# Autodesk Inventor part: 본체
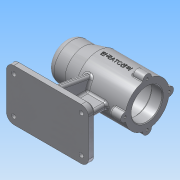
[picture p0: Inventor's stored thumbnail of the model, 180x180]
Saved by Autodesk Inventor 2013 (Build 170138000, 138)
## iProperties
Created: 2019-07
Part Number: 본체
Material: 알루미늄 6061
Document SubType Name: Modeling
Designer: Administrator
Density: 2.71 g/cm^3
Mass: 658.039 g
Surface Area: 650.148 cm^2
Volume: 242.819 cm^3
Author: Administrator
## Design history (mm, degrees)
sketch "스케치1"
  geometry: L1 (56, 0)-(-56, 0); L2 (56, 0)-(56, 30); L3 (56, 30)-(-11, 30); L4 (-11, 30)-(-31, 25); L5 (-31, 25)-(-56, 25); L6 (-56, 25)-(-56, 0); 2 further points
  constraints: 12 end point, 2 parallel, 2 perpendicular, 1 coincident, 1 horizontal, 1 midpoint
  dimensions: "d1" = 60 diameter of L3 L1; "d3" = 50 diameter of L5 L1; "d4" = 25 distance of L4.end L5.end; "d5" = 45 distance from line of L6 L3.end; "d7" = 112 distance between parallel lines of L6 L2
revolve "회전1" sketch "스케치1" stored, may be unused: angle "d8" = 90 deg
node "작업 평면1"
sketch "스케치2"
  geometry: L1 (-56, 35)-(56, 35); L2 (56, 35)-(56, -35); L3 (56, -35)-(-56, -35); L4 (-56, -35)-(-56, 35); 3 further points
  constraints: 8 end point, 2 midpoint, 2 parallel, 1 horizontal, 1 horizontal alignment, 1 perpendicular, 1 vertical alignment
  dimensions: "d10" = 112 distance of L1.start L1.end; "d12" = 70 distance of L3.end L1.start
extrude "돌출1" join sketch "스케치2" distance "d13" = 10; taper "d14" = 0 deg
sketch "스케치3"
  geometry: L1 (31, 0)-(31, -70); L2 (31, -70)-(-36, -70); L3 (-36, -70)-(-10.522, 0); L4 (-10.522, 0)-(31, 0); L5 (56, -80)-(56, -70) reference; L6 (-56, -80)-(-56, -70) reference; L7 (56, -70)-(-56, -70) reference; 3 further points
  constraints: 8 end point, 2 horizontal alignment, 2 midpoint, 1 parallel, 1 perpendicular, 1 vertical
  dimensions: "d15" = 25 distance between parallel lines of L5 L1; "d16" = 20 distance from line of L2.end L6; "d17" = 110 deg angle of L3 L7
extrude "돌출2" join sketch "스케치3" distance "d18" = 4; taper "d20" = 0 deg; dims "d19" = 4, "d21" = 0
sketch "스케치4"
  geometry: L1 (-22.666, 19.654)-(-70, 28); L2 (-70, -35)-(-70, 35) reference; L3 (-80, 35)-(-70, 35) reference; A1 r 30 centre (0, 0) between (-29.732, -4) and (-29.732, 4) reference; 1 further point
  constraints: 2 end point, 1 point on circle, 1 point on line
  dimensions: "d22" = 100 deg angle of L1 L2; "d23" = 7 distance from line of L1.end L3
feature "리브1" sketch "스케치4" dims "d24" = 1, "d25" = 8, "d26" = 0, "d27" = 0, "d28" = 1, "d29" = 1
sketch "스케치5"
  geometry: L1 (56, -30)-(56, 30) reference; L2 (-56, -25)-(-56, 25) reference; L3 (56, 0)-(-50, 0); L4 (56, 0)-(56, 21); L5 (56, 21)-(41, 21); L6 (41, 21)-(41, 24); L7 (41, 24)-(-13, 24); L8 (-13, 24)-(-13, 21); L9 (-13, 21)-(-25, 21); L10 (-25, 21)-(-25, 17.5); L11 (-25, 17.5)-(-43, 17.5); L12 (-43, 17.5)-(-43, 16); L13 (-43, 16)-(-47, 16); L14 (-47, 16)-(-47, 10.5); L15 (-47, 10.5)-(-50, 10.5); L16 (-50, 10.5)-(-50, 0); 1 further point
  constraints: 28 end point, 8 parallel, 4 perpendicular, 1 collinear, 1 midpoint, 1 point on line
  dimensions: "d30" = 42 diameter of L5 L3; "d32" = 48 diameter of L7 L3; "d33" = 42 diameter of L9 L3; "d34" = 21 diameter of L15 L3; "d35" = 32 diameter of L13 L3; "d36" = 35 diameter of L11 L3; "d37" = 3 distance of L14.end L15.end; "d38" = 4 distance of L12.end L13.end; "d39" = 18 distance of L10.end L11.end; "d40" = 12 distance of L8.end L9.end; "d41" = 54 distance of L6.end L7.end; "d42" = 15 distance of L4.end L5.end
revolve "회전2" sketch "스케치5" stored, may be unused: angle "d43" = 90 deg
sketch "스케치6"
  geometry: C1 r 21 at (0, 0) reference; C2 r 6 at (0, 30); 1 further point
  constraints: 2 vertical alignment, 1 centre point, 1 other
  dimensions: "d44" = 12 diameter of C2
extrude "돌출3" join sketch "스케치6" distance "d45" = 16; taper "d46" = 0 deg
fillet "모깎기1" dims "d50" = 10, "d51" = 3, "d56" = 0.3
fillet "모깎기2" dims "d52" = 1, "d57" = 3
chamfer "모따기1" distance "d53" = 3; stored, may be unused: second distance "d54" = 2, angle "d55" = 45 deg
sketch "스케치7"
  geometry: A1 r 7 centre (46, -25) between (46, -32) and (53, -25) reference; A2 r 7 centre (46, 25) between (53, 25) and (46, 32) reference; A3 r 7 centre (-46, 25) between (-46, 32) and (-53, 25) reference; A4 r 7 centre (-46, -25) between (-53, -25) and (-46, -32) reference; 1 further point
hole "구멍1" sketch "스케치7" at (-46, 25), (-46, -25), (46, -25), (46, 25) diameter "d58" = 6; stored, may be unused: countersink angle "d62" = 90 deg, drill point angle "d64" = 118 deg; dims "d59" = 6, "d60" = 4, "d61" = 2, "d63" = 8
sketch "스케치8"
  geometry: A1 r 6 centre (30, 30) between (35.998, 30.171) and (24.002, 30.171) reference; A2 r 6 centre (0, 0) between (-0.171, 5.998) and (-0.171, -5.998) reference; A3 r 6 centre (30, -30) between (24.002, -30.171) and (35.998, -30.171) reference; A4 r 6 centre (60, 0) between (60.171, -5.998) and (60.171, 5.998) reference
hole "구멍2" sketch "스케치8" at (30, 30), (0, 0), (30, -30), (60, 0) diameter "d65" = 3.242; stored, may be unused: countersink angle "d69" = 90 deg, drill point angle "d71" = 118 deg; dims "d66" = 8, "d67" = 4, "d68" = 2, "d70" = 11
node "작업 평면2"
sketch "스케치9"
  geometry: L1 (33.5, 5.998)-(33.5, -5.998) reference; 2 further points
  constraints: 1 horizontal alignment, 1 other
  dimensions: "d72" = 42 distance from line of L1 point (-8.5, 0)
feature "엠보싱1" sketch "스케치9" dims "d73" = 0.5, "d74" = 0
chamfer "모따기2" distance "d75" = 1; stored, may be unused: second distance "d76" = 2, angle "d77" = 45 deg
node "솔리드1"
mirror "대칭1"
pattern_circular "원형 패턴1" dims angle "d48" = 360 deg
